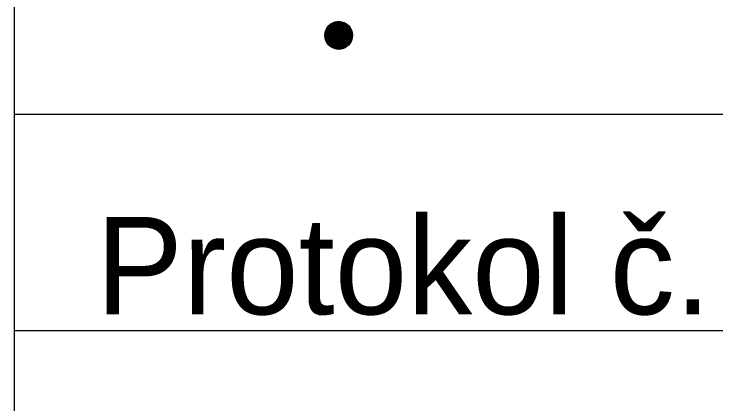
# Model space of a CAD drawing. Extents: x -497549 to -497344, y -1086547 to -1086398.
# Drawn here: x -497399.21 to -497391.99, y -1086529.19 to -1086525.19 of the extents above; entities that cross this region are included whole.
import ezdxf

# ---------------------------------------------------------------- set-up
doc = ezdxf.new("R2010")
doc.units = 0
doc.layers.add('Vrstva 63', color=7, linetype='Continuous')

msp = doc.modelspace()

# ---------------------------------------------------------------- linework, layer by layer
at = {"layer": 'Vrstva 63'}
for p, q in [((-497396.0126, -1086525.4074), (-497395.8707, -1086525.2656)), ((-497396.0125, -1086525.4113), (-497395.8668, -1086525.2656)), ((-497396.0125, -1086525.4094), (-497395.8687, -1086525.2656)), ((-497396.0125, -1086525.4053), (-497395.8728, -1086525.2656)), ((-497396.0125, -1086525.4033), (-497395.8748, -1086525.2656)), ((-497396.0124, -1086525.4133), (-497395.8648, -1086525.2657)), ((-497396.0124, -1086525.4012), (-497395.8769, -1086525.2657)), ((-497396.0124, -1086525.4152), (-497395.8629, -1086525.2658)), ((-497396.0123, -1086525.3991), (-497395.879, -1086525.2658)), ((-497396.0122, -1086525.4171), (-497395.861, -1086525.2659)), ((-497396.0121, -1086525.419), (-497395.8591, -1086525.266)), ((-497396.0121, -1086525.3969), (-497395.8812, -1086525.266)), ((-497396.012, -1086525.3947), (-497395.8834, -1086525.2662)), ((-497396.0119, -1086525.4208), (-497395.8573, -1086525.2662)), ((-497396.0118, -1086525.4227), (-497395.8554, -1086525.2664)), ((-497396.0117, -1086525.3925), (-497395.8856, -1086525.2664)), ((-497396.0116, -1086525.4245), (-497395.8536, -1086525.2666)), ((-497396.0115, -1086525.3902), (-497395.8879, -1086525.2666)), ((-497396.0113, -1086525.4263), (-497395.8518, -1086525.2668)), ((-497396.0112, -1086525.3879), (-497395.8902, -1086525.2669)), ((-497396.0111, -1086525.428), (-497395.8501, -1086525.267)), ((-497396.0108, -1086525.4298), (-497395.8483, -1086525.2673)), ((-497396.0108, -1086525.3855), (-497395.8926, -1086525.2673)), ((-497396.0105, -1086525.4315), (-497395.8466, -1086525.2676)), ((-497396.0104, -1086525.3831), (-497395.895, -1086525.2677)), ((-497396.0102, -1086525.4332), (-497395.8449, -1086525.2679)), ((-497396.01, -1086525.3806), (-497395.8975, -1086525.2682)), ((-497396.0099, -1086525.4349), (-497395.8432, -1086525.2682)), ((-497396.0096, -1086525.4366), (-497395.8415, -1086525.2685)), ((-497396.0094, -1086525.3781), (-497395.9, -1086525.2687)), ((-497396.0092, -1086525.4382), (-497395.8399, -1086525.2689)), ((-497396.0089, -1086525.3755), (-497395.9026, -1086525.2692)), ((-497396.0089, -1086525.4399), (-497395.8382, -1086525.2693)), ((-497396.0085, -1086525.4415), (-497395.8366, -1086525.2696)), ((-497396.0082, -1086525.3729), (-497395.9052, -1086525.2699)), ((-497396.0081, -1086525.4431), (-497395.835, -1086525.27)), ((-497396.0076, -1086525.4447), (-497395.8334, -1086525.2705)), ((-497396.0075, -1086525.3701), (-497395.908, -1086525.2706)), ((-497396.0072, -1086525.4463), (-497395.8318, -1086525.2709)), ((-497396.0068, -1086525.4478), (-497395.8303, -1086525.2714)), ((-497396.0067, -1086525.3673), (-497395.9108, -1086525.2714)), ((-497396.0063, -1086525.4494), (-497395.8287, -1086525.2718)), ((-497396.0058, -1086525.4509), (-497395.8272, -1086525.2723)), ((-497396.0058, -1086525.3644), (-497395.9137, -1086525.2723)), ((-497396.0053, -1086525.4524), (-497395.8257, -1086525.2728)), ((-497396.0048, -1086525.4539), (-497395.8242, -1086525.2733)), ((-497396.0048, -1086525.3614), (-497395.9167, -1086525.2733)), ((-497396.0043, -1086525.4554), (-497395.8227, -1086525.2738)), ((-497396.0038, -1086525.4569), (-497395.8212, -1086525.2744)), ((-497396.0037, -1086525.3583), (-497395.9198, -1086525.2744)), ((-497396.0032, -1086525.4584), (-497395.8198, -1086525.2749)), ((-497396.0026, -1086525.4598), (-497395.8183, -1086525.2755)), ((-497396.0024, -1086525.355), (-497395.9231, -1086525.2757)), ((-497396.0021, -1086525.4612), (-497395.8169, -1086525.276)), ((-497396.0015, -1086525.4627), (-497395.8154, -1086525.2766)), ((-497396.001, -1086525.3516), (-497395.9265, -1086525.2771)), ((-497396.0009, -1086525.4641), (-497395.814, -1086525.2772)), ((-497396.0003, -1086525.4655), (-497395.8126, -1086525.2778)), ((-497395.9996, -1086525.4669), (-497395.8112, -1086525.2785)), ((-497395.9994, -1086525.348), (-497395.9302, -1086525.2787)), ((-497395.999, -1086525.4682), (-497395.8099, -1086525.2791)), ((-497395.9983, -1086525.4696), (-497395.8085, -1086525.2798)), ((-497395.9977, -1086525.4709), (-497395.8072, -1086525.2804)), ((-497395.9975, -1086525.3441), (-497395.934, -1086525.2806)), ((-497395.997, -1086525.4723), (-497395.8058, -1086525.2811)), ((-497395.9963, -1086525.4736), (-497395.8045, -1086525.2818)), ((-497395.9956, -1086525.4749), (-497395.8032, -1086525.2825)), ((-497395.9953, -1086525.3399), (-497395.9382, -1086525.2828)), ((-497395.9949, -1086525.4762), (-497395.8019, -1086525.2832)), ((-497395.9942, -1086525.4775), (-497395.8006, -1086525.2839)), ((-497395.9935, -1086525.4788), (-497395.7993, -1086525.2846)), ((-497395.9927, -1086525.4801), (-497395.798, -1086525.2854)), ((-497395.9927, -1086525.3352), (-497395.9429, -1086525.2854)), ((-497395.992, -1086525.4813), (-497395.7968, -1086525.2861)), ((-497395.9912, -1086525.4826), (-497395.7955, -1086525.2869)), ((-497395.9904, -1086525.4838), (-497395.7943, -1086525.2877)), ((-497395.9896, -1086525.485), (-497395.7931, -1086525.2885)), ((-497395.9894, -1086525.3299), (-497395.9482, -1086525.2887)), ((-497395.9888, -1086525.4862), (-497395.7919, -1086525.2893)), ((-497395.988, -1086525.4874), (-497395.7907, -1086525.2901)), ((-497395.9872, -1086525.4886), (-497395.7895, -1086525.2909)), ((-497395.9864, -1086525.4898), (-497395.7883, -1086525.2917)), ((-497395.9856, -1086525.491), (-497395.7871, -1086525.2926)), ((-497395.9848, -1086525.3233), (-497395.9548, -1086525.2933)), ((-497395.9847, -1086525.4922), (-497395.786, -1086525.2934)), ((-497395.9838, -1086525.4933), (-497395.7848, -1086525.2943)), ((-497395.983, -1086525.4945), (-497395.7837, -1086525.2951)), ((-497395.9821, -1086525.4956), (-497395.7825, -1086525.296)), ((-497395.9812, -1086525.4967), (-497395.7814, -1086525.2969)), ((-497395.9803, -1086525.4978), (-497395.7803, -1086525.2978)), ((-497395.9794, -1086525.4989), (-497395.7792, -1086525.2987)), ((-497395.9785, -1086525.5), (-497395.7781, -1086525.2996)), ((-497395.9775, -1086525.5011), (-497395.777, -1086525.3006)), ((-497395.9766, -1086525.5021), (-497395.776, -1086525.3015)), ((-497395.9757, -1086525.3122), (-497395.9659, -1086525.3024)), ((-497395.9756, -1086525.5032), (-497395.7749, -1086525.3025)), ((-497395.9747, -1086525.5043), (-497395.7739, -1086525.3034)), ((-497395.9737, -1086525.5053), (-497395.7728, -1086525.3044)), ((-497395.9727, -1086525.5063), (-497395.7718, -1086525.3054)), ((-497395.9717, -1086525.5073), (-497395.7708, -1086525.3064)), ((-497395.9707, -1086525.5084), (-497395.7698, -1086525.3074)), ((-497395.9697, -1086525.5094), (-497395.7688, -1086525.3084)), ((-497395.9687, -1086525.5103), (-497395.7678, -1086525.3094)), ((-497395.9677, -1086525.5113), (-497395.7668, -1086525.3104)), ((-497395.9666, -1086525.5123), (-497395.7658, -1086525.3115)), ((-497395.9656, -1086525.5132), (-497395.7649, -1086525.3125)), ((-497395.9645, -1086525.5142), (-497395.7639, -1086525.3136)), ((-497395.9634, -1086525.5151), (-497395.763, -1086525.3147)), ((-497395.9623, -1086525.5161), (-497395.7621, -1086525.3158)), ((-497395.9613, -1086525.517), (-497395.7611, -1086525.3169)), ((-497395.9601, -1086525.5179), (-497395.7602, -1086525.318)), ((-497395.959, -1086525.5188), (-497395.7593, -1086525.3191)), ((-497395.9579, -1086525.5197), (-497395.7584, -1086525.3202)), ((-497395.9568, -1086525.5205), (-497395.7576, -1086525.3213)), ((-497395.9556, -1086525.5214), (-497395.7567, -1086525.3225)), ((-497395.9545, -1086525.5223), (-497395.7558, -1086525.3236)), ((-497395.9533, -1086525.5231), (-497395.755, -1086525.3248)), ((-497395.9521, -1086525.5239), (-497395.7542, -1086525.326)), ((-497395.9509, -1086525.5248), (-497395.7533, -1086525.3272)), ((-497395.9497, -1086525.5256), (-497395.7525, -1086525.3284)), ((-497395.9485, -1086525.5264), (-497395.7517, -1086525.3296)), ((-497395.9473, -1086525.5272), (-497395.7509, -1086525.3308)), ((-497395.9461, -1086525.528), (-497395.7501, -1086525.332)), ((-497395.9449, -1086525.5287), (-497395.7494, -1086525.3333)), ((-497395.9436, -1086525.5295), (-497395.7486, -1086525.3345)), ((-497395.9423, -1086525.5302), (-497395.7479, -1086525.3358)), ((-497395.9411, -1086525.531), (-497395.7471, -1086525.337)), ((-497395.9398, -1086525.5317), (-497395.7464, -1086525.3383)), ((-497395.9385, -1086525.5324), (-497395.7457, -1086525.3396)), ((-497395.9372, -1086525.5331), (-497395.745, -1086525.3409)), ((-497395.9359, -1086525.5338), (-497395.7443, -1086525.3423)), ((-497395.9345, -1086525.5345), (-497395.7436, -1086525.3436)), ((-497395.9332, -1086525.5352), (-497395.7429, -1086525.3449)), ((-497395.9318, -1086525.5358), (-497395.7423, -1086525.3463)), ((-497395.9305, -1086525.5365), (-497395.7416, -1086525.3476)), ((-497395.9291, -1086525.5371), (-497395.741, -1086525.349)), ((-497395.9277, -1086525.5377), (-497395.7404, -1086525.3504)), ((-497395.9263, -1086525.5383), (-497395.7398, -1086525.3518)), ((-497395.9249, -1086525.5389), (-497395.7392, -1086525.3532)), ((-497395.9235, -1086525.5395), (-497395.7386, -1086525.3547)), ((-497395.922, -1086525.5401), (-497395.738, -1086525.3561)), ((-497395.9206, -1086525.5406), (-497395.7375, -1086525.3576)), ((-497395.9191, -1086525.5412), (-497395.7369, -1086525.359)), ((-497395.9176, -1086525.5417), (-497395.7364, -1086525.3605)), ((-497395.9161, -1086525.5422), (-497395.7359, -1086525.362)), ((-497395.9146, -1086525.5427), (-497395.7354, -1086525.3635)), ((-497395.9131, -1086525.5432), (-497395.7349, -1086525.365)), ((-497395.9115, -1086525.5437), (-497395.7344, -1086525.3666)), ((-497395.91, -1086525.5442), (-497395.734, -1086525.3681)), ((-497395.9084, -1086525.5446), (-497395.7335, -1086525.3697)), ((-497395.9068, -1086525.545), (-497395.7331, -1086525.3713)), ((-497395.9052, -1086525.5454), (-497395.7327, -1086525.3729)), ((-497395.9036, -1086525.5458), (-497395.7323, -1086525.3745)), ((-497395.902, -1086525.5462), (-497395.7319, -1086525.3761)), ((-497395.9004, -1086525.5466), (-497395.7315, -1086525.3778)), ((-497395.8987, -1086525.5469), (-497395.7312, -1086525.3794)), ((-497395.897, -1086525.5473), (-497395.7308, -1086525.3811)), ((-497395.8953, -1086525.5476), (-497395.7305, -1086525.3828)), ((-497395.8936, -1086525.5479), (-497395.7302, -1086525.3845)), ((-497395.8919, -1086525.5482), (-497395.73, -1086525.3862)), ((-497395.8901, -1086525.5484), (-497395.7297, -1086525.388)), ((-497395.8883, -1086525.5486), (-497395.7295, -1086525.3898)), ((-497395.8865, -1086525.5489), (-497395.7293, -1086525.3916)), ((-497395.8847, -1086525.5491), (-497395.7291, -1086525.3934)), ((-497395.8829, -1086525.5492), (-497395.7289, -1086525.3952)), ((-497395.881, -1086525.5494), (-497395.7287, -1086525.3971)), ((-497395.8791, -1086525.5495), (-497395.7286, -1086525.399)), ((-497395.8772, -1086525.5496), (-497395.7285, -1086525.4009)), ((-497395.8753, -1086525.5497), (-497395.7284, -1086525.4028)), ((-497395.8733, -1086525.5497), (-497395.7284, -1086525.4048)), ((-497395.8714, -1086525.5498), (-497395.7283, -1086525.4068)), ((-497395.8693, -1086525.5498), (-497395.7283, -1086525.4088)), ((-497395.8673, -1086525.5497), (-497395.7284, -1086525.4108)), ((-497395.8652, -1086525.5497), (-497395.7284, -1086525.4129)), ((-497395.8631, -1086525.5496), (-497395.7285, -1086525.415)), ((-497395.861, -1086525.5495), (-497395.7287, -1086525.4171)), ((-497395.8588, -1086525.5493), (-497395.7288, -1086525.4193)), ((-497395.8566, -1086525.5491), (-497395.729, -1086525.4215)), ((-497395.8544, -1086525.5489), (-497395.7293, -1086525.4238)), ((-497395.8521, -1086525.5486), (-497395.7295, -1086525.426)), ((-497395.8497, -1086525.5483), (-497395.7299, -1086525.4284)), ((-497395.8473, -1086525.5479), (-497395.7302, -1086525.4308)), ((-497395.8449, -1086525.5475), (-497395.7306, -1086525.4332)), ((-497395.8424, -1086525.547), (-497395.7311, -1086525.4357)), ((-497395.8399, -1086525.5464), (-497395.7317, -1086525.4382)), ((-497395.8373, -1086525.5458), (-497395.7323, -1086525.4408)), ((-497395.8346, -1086525.5452), (-497395.7329, -1086525.4435)), ((-497395.8318, -1086525.5444), (-497395.7337, -1086525.4463)), ((-497395.829, -1086525.5436), (-497395.7345, -1086525.4491)), ((-497395.826, -1086525.5427), (-497395.7355, -1086525.4521)), ((-497395.823, -1086525.5416), (-497395.7365, -1086525.4551)), ((-497395.8198, -1086525.5404), (-497395.7377, -1086525.4583)), ((-497395.8165, -1086525.5391), (-497395.739, -1086525.4617)), ((-497395.8129, -1086525.5376), (-497395.7405, -1086525.4652)), ((-497395.8092, -1086525.5359), (-497395.7422, -1086525.4689)), ((-497395.8052, -1086525.5339), (-497395.7442, -1086525.4729)), ((-497395.8009, -1086525.5316), (-497395.7465, -1086525.4772)), ((-497395.796, -1086525.5287), (-497395.7494, -1086525.4821)), ((-497395.7903, -1086525.525), (-497395.7531, -1086525.4879)), ((-497395.7827, -1086525.5195), (-497395.7586, -1086525.4954)), ((-497399.206, -1086526.2185), (-497349.206, -1086526.2185)), ((-497399.206, -1086528.4385), (-497349.206, -1086528.4385))]:
    msp.add_line(p, q, dxfattribs=at)
msp.add_lwpolyline([(-497349.206, -1086521.4769), (-497399.206, -1086521.4769), (-497399.206, -1086541.7725)], dxfattribs=at)
msp.add_circle((-497395.8704, -1086525.4077), 0.1421, dxfattribs=at)

# ---------------------------------------------------------------- texts
msp.add_text('Protokol č.', height=0.999996, dxfattribs=at).set_placement((-497398.3633, -1086528.273))

doc.saveas('drawing.dxf')
